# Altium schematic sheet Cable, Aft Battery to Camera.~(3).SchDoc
size Tabloid; Organization: Monterey Bay Aquarium Research Institute; Address1: 7700 Sandholdt Rd; Address2: Moss Landing, CA 95039-9644; Author: Hans Thomas; CompanyName: MBARI; DrawnBy: Hans Thomas; Engineer: Hans Thomas
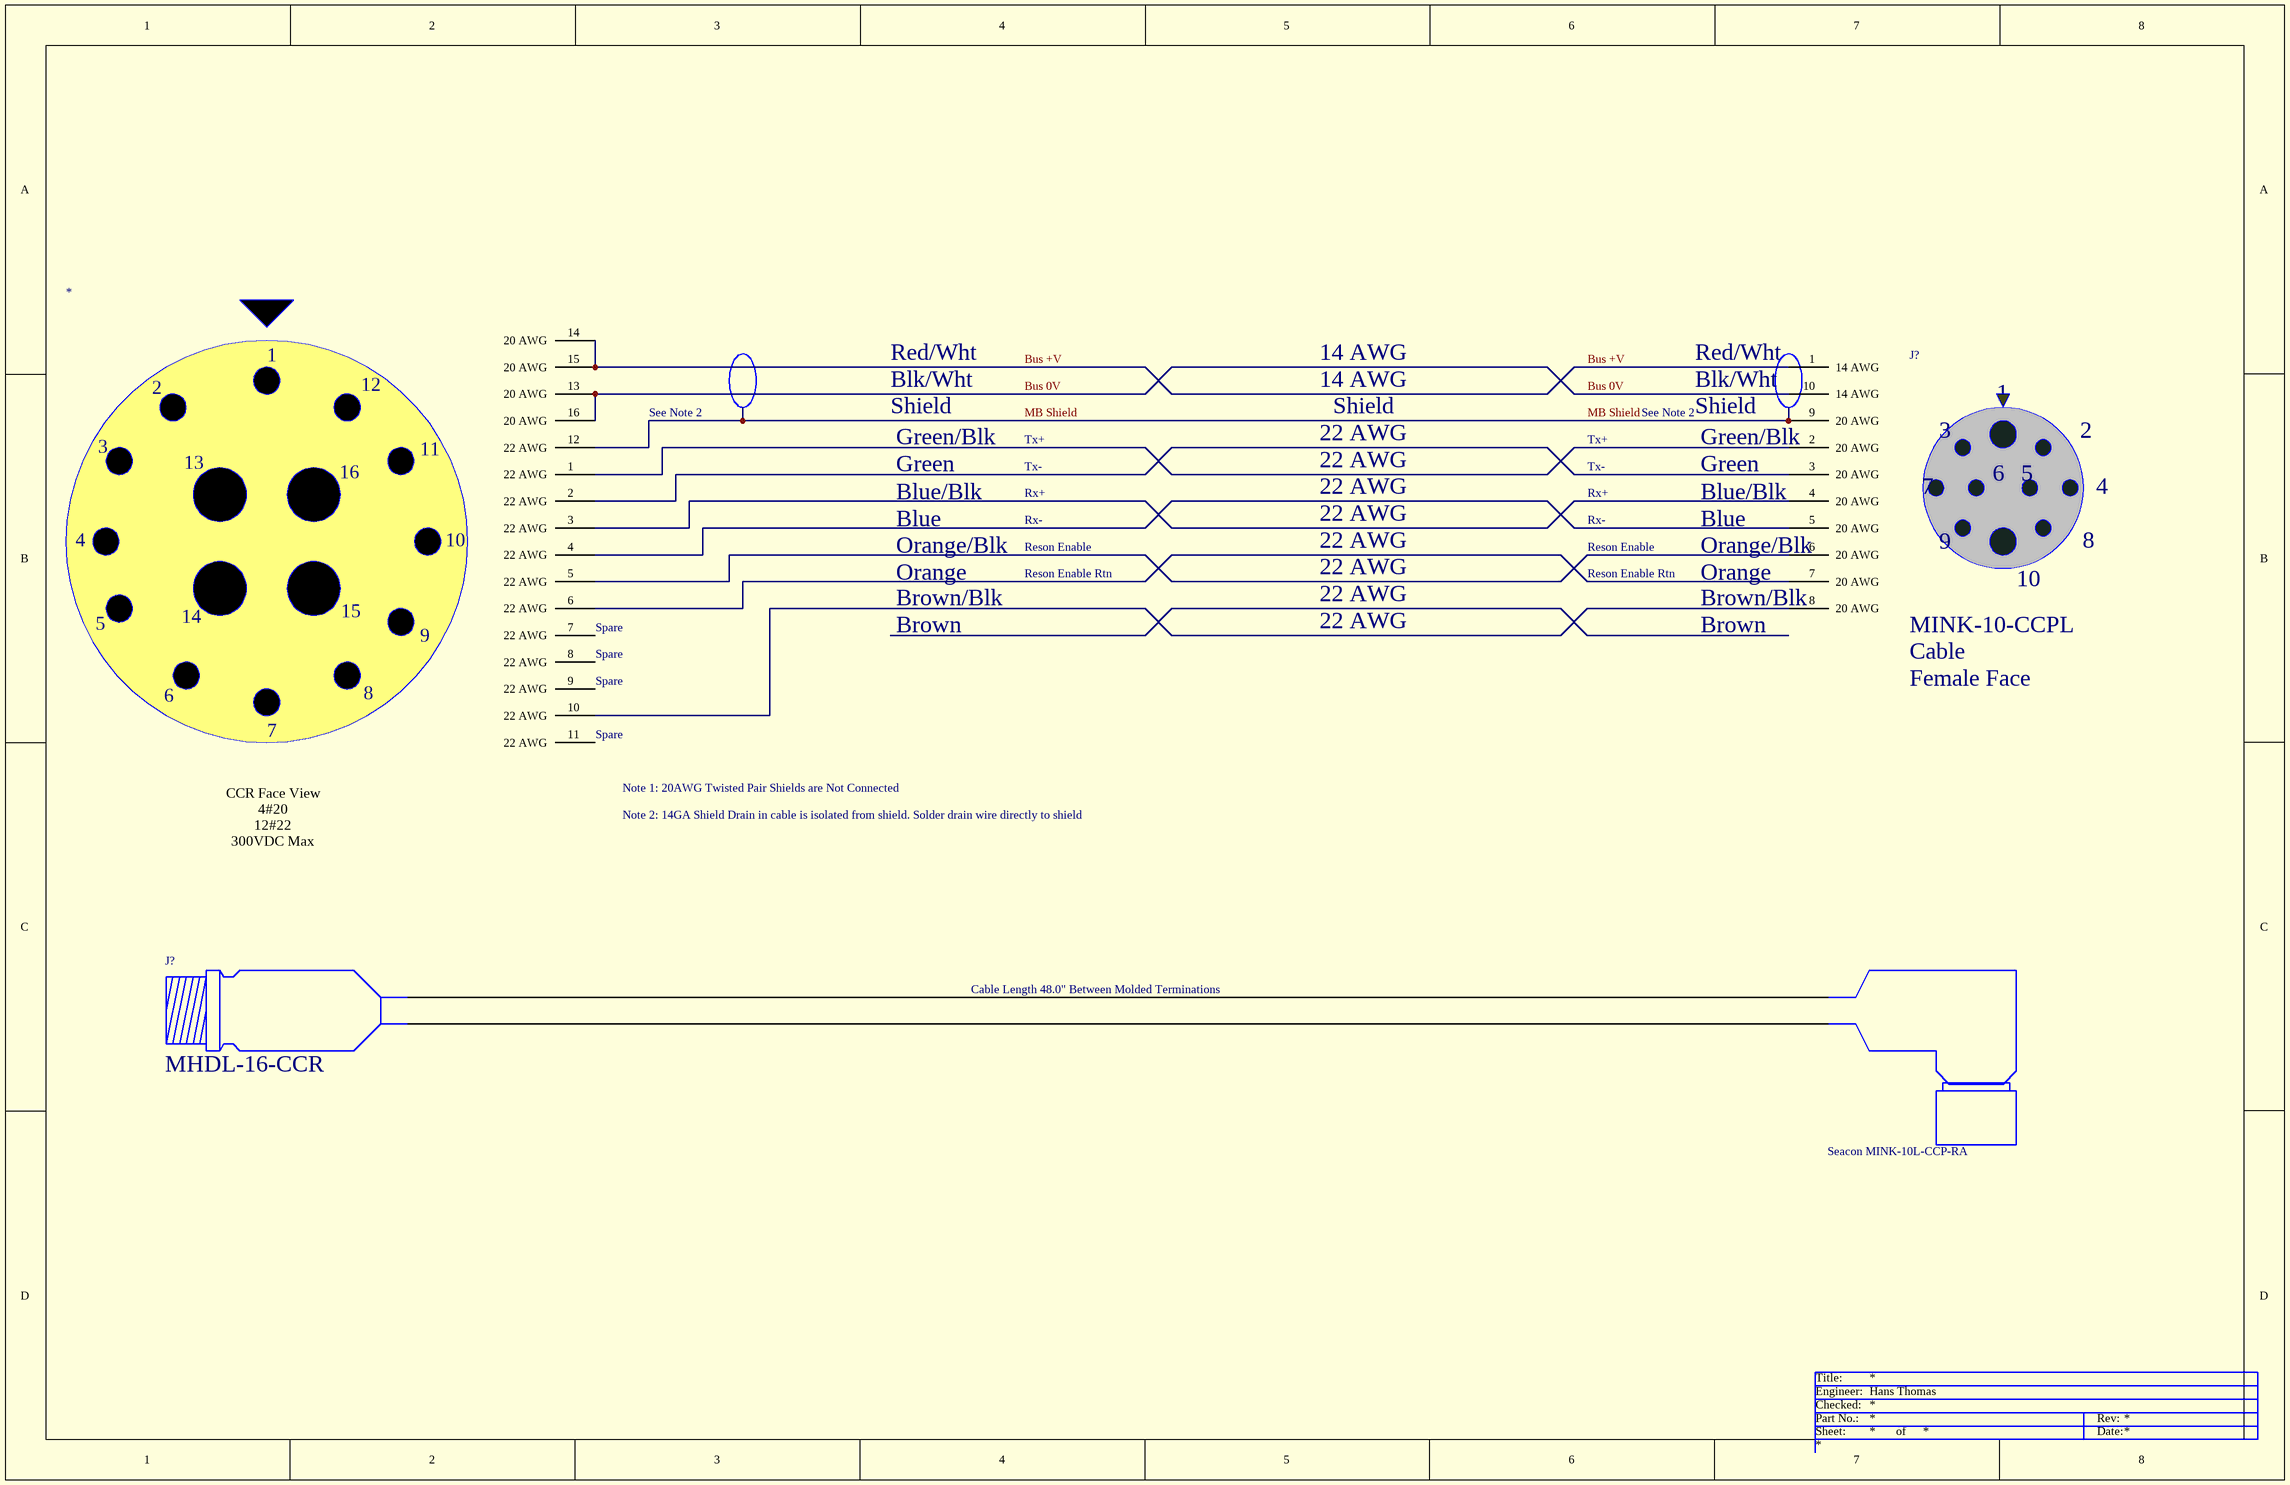
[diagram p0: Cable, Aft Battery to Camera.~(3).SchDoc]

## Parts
(Parts that share a designator on the sheet are numbered #1, #2 ... from top to bottom, then left to right.)
*#1  MHDL-16-CCR-SOLDER  (value not drawn)
*#2  Seacon MINK-10L-CCP-RA
J?#1  MINK-10-CCPL  DescSheet: Cable  View: Female Face
J?#2  MHDL-16-CCR

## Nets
Bus 0V: *#1.13(20_AWG) *#1.16(20_AWG) J?#1.10(14_AWG)
Bus +V: *#1.14(20_AWG) *#1.15(20_AWG) J?#1.1(14_AWG)
MB Shield: *#1.12(22_AWG) J?#1.9(20_AWG)
Net*#1_1: *#1.1(22_AWG) J?#1.2(20_AWG)
Net*#1_2: *#1.2(22_AWG) J?#1.3(20_AWG)
Net*#1_3: *#1.3(22_AWG) J?#1.4(20_AWG)
Net*#1_4: *#1.4(22_AWG) J?#1.5(20_AWG)
Net*#1_5: *#1.5(22_AWG) J?#1.6(20_AWG)
Net*#1_6: *#1.6(22_AWG) J?#1.7(20_AWG)
Net*#1_10: *#1.10(22_AWG) J?#1.8(20_AWG)

Not connected (* = marked no-connect by the designer): *#1 7(22_AWG) 8(22_AWG) 9(22_AWG) 11(22_AWG)

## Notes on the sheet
- Red/Wht
- 14 AWG
- (near J?#1) Red/Wht
- See Note 2
- Blk/Wht
- Shield
- (near J?#1) Blk/Wht
- Green
- Blue/Blk
- Green/Blk
- Tx+
- Tx-
- Rx+
- 22 AWG
- (near J?#1) Blue/Blk
- (near J?#1) Green/Blk
- Blue
- Orange/Blk
- Rx-
- Reson Enable
- (near J?#1) Orange/Blk
- (near *#1) Spare
- Brown/Blk
- Orange
- Brown
- Reson Enable Rtn
- (near J?#1) Brown/Blk
- Note 1: 20AWG Twisted Pair Shields are Not Connected
- Note 2: 14GA Shield Drain in cable is isolated from shield. Solder drain wire directly to shield
- Cable Length 48.0" Between Molded Terminations

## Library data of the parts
*#2 = CONN-MIN-CCP-RA-LARGE
J?#1 = SEACON-MINK-10-CCP-SOC: Seacon MINK-10/L-CCP Connector
J?#2 = CONN-MIN-CCR-LARGE: Seacon MIN Connector CCR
